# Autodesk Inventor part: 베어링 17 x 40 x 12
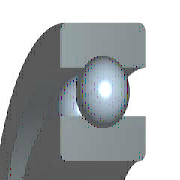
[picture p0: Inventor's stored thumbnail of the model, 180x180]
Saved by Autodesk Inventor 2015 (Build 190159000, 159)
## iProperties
IsCustomPart: 1
Created: 2012-02
Part Number: 베어링 17 x 40 x 12
Material: 강철, 연강
Description: 깊은 그루브 볼 베어링
Document SubType Name: Modeling
Standard: KS B 2023
Designer: mduedu
Standards Organization: KS
Language: ko-KR
Size Designation: 6203 - 17 x 40 x 12
Categories: <MemberInstance><Categories><Category DisplayName="샤프트 부품" InternalName="7f7aeb1f-a693-4053-b835-cee3144e0d98" Mnemonic="SHFT"><Category DisplayName="베어링" Inter
Density: 1 g/cm^3
Appearance: 노란색
Author: mduedu
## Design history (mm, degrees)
sketch "스케치" dims "d0" = 5.98 (= -0.26 x WD + 0.26 x BD)
  geometry: L1 (3.01, 14.25)-(8.99, 14.25); L2 (6, 14.25)-(6, 11.26); L3 (6, 14.25)-(6, 17.24); L4 (3.778, 12.249)-(0, 12.249); L5 (0, 8.5)-(12, 8.5); L6 (3.778, 16.251)-(0, 16.251); L7 (0, 20)-(12, 20); L8 (12, 8.5)-(12, 12.249); L9 (8.222, 12.249)-(12, 12.249); L10 (8.222, 16.251)-(12, 16.251); L11 (12, 20)-(12, 16.251); L12 (-1.4, 0)-(8.4, 0) reference; L13 (0, -0.3)-(0, 5.3) reference
  constraints: 22 end point, 4 point on line, 2 collinear, 2 perpendicular, 2 symmetric about line, 1 midpoint, 1 parallel, 14 other
  dimensions: "d9" = 17 diameter of L5 L12 (= WD); "d11" = 40 diameter of L7 L12 (= BD); "d12" = 12 distance between parallel lines of L8 L13 (= KB); "d13" = 24.498 diameter of L9 L12 (= 0.326 x BD + 0.674 x WD)
revolve "본체" stored, may be unused: angle "d6" = 90 deg
revolve "볼" stored, may be unused: angle "d7" = 90 deg
pattern_circular "IDS_ARRAYBALL[SIMPL:T]" dims angle "d3" = 360 deg
body "Solid1"
fillet "모깎기1" dims "d1" = 0.6 (= KRS)
other parameters: "WD" = 17 [user parameter; used in 5 equation terms], "BD" = 40 [user parameter; used in 5 equation terms], "KB" = 12 [user parameter; used in 1 equation term], "KRS" = 0.6 [user parameter; used in 1 equation term], "d4" = 0, "d5" = 0, "d8" = 0, "d14" = 0, "d15" = 0, "BBA" = 0 [user parameter], "BC0" = 4750000 [user parameter], "BC" = 9560000 [user parameter], "WR" = 8.5 (= 0.5 x WD) [user parameter]
